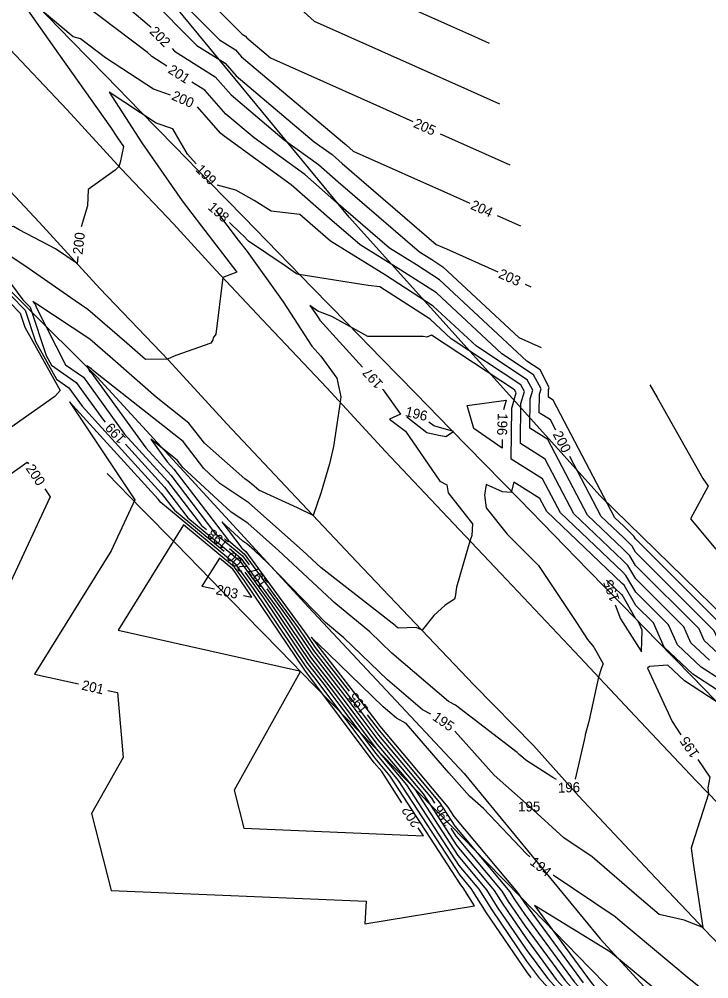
# Model space of a CAD drawing. Extents: x 2086416 to 2115205, y 575507 to 632762.
# Drawn here: x 2110108.6 to 2110247.4, y 582081.1 to 582274.4 of the extents above; entities that cross this region are included whole.
import ezdxf

# ---------------------------------------------------------------- set-up
doc = ezdxf.new("R2010")
doc.units = 0
for name, color, linetype in [('DTM Contours Major', 7, 'Continuous'), ('DTM Contours Major Text', 7, 'Continuous'), ('DTM Contours Minor', 7, 'Continuous'), ('DTM Contours Minor Text', 7, 'Continuous'), ('Exist Hydrographic FEMA Cross Section', 7, 'Continuous'), ('Exist Roads EOP', 7, 'Continuous'), ('Exist Vegetation Woods Line', 7, 'Continuous')]:
    doc.layers.add(name, color=color, linetype=linetype)

msp = doc.modelspace()

# ---------------------------------------------------------------- linework, layer by layer
at = {"layer": 'DTM Contours Major'}
for points in [[(2110109.16, 582313.08), (2110112.32, 582311.02), (2110129.31, 582294.29), (2110131.09, 582292.62), (2110132.72, 582292.09), (2110134.17, 582290.85), (2110153.5, 582271.34), (2110154.17, 582270.92), (2110154.43, 582270.61), (2110159.2, 582266.6), (2110181.16, 582256.77), (2110187.89, 582253.76)], [(2110139.1, 582259.08), (2110135.66, 582260.25), (2110126, 582266.59), (2110120.98, 582270.39), (2110119.48, 582270.82), (2110107.88, 582280.62), (2110107.79, 582280.67), (2110107.65, 582280.8), (2110106.39, 582281.73), (2110107.13, 582280.82), (2110107.89, 582279.73), (2110116.56, 582267.38), (2110127.02, 582252.6), (2110128.41, 582250.45), (2110129.6, 582248.74), (2110128.93, 582245.49), (2110128.68, 582244.73), (2110127.92, 582243.98), (2110122.51, 582240.09), (2110122.35, 582236.81), (2110121.07, 582232.55)], [(2110120.4, 582226.6), (2110120.27, 582225.14), (2110115.94, 582228.14), (2110108.58, 582231.97), (2110107.48, 582232.63), (2110107.15, 582232.52), (2110098.82, 582237.61), (2110091.52, 582245.28), (2110084.17, 582251.94), (2110069.86, 582265.54), (2110068.65, 582266.59), (2110065.58, 582269.39), (2110068.47, 582266.29), (2110068.49, 582266.13), (2110068.51, 582266.04), (2110068.58, 582265.96), (2110068.8, 582265.85), (2110068.96, 582265.74), (2110080.07, 582251.64), (2110082.51, 582248.8), (2110083.01, 582248.14)], [(2110216.68, 582191.59), (2110215.58, 582193.69), (2110213.31, 582195.12), (2110213.35, 582198.82), (2110213.67, 582199.92), (2110212.19, 582202.73), (2110205.75, 582206.99), (2110192.62, 582219.23), (2110185.46, 582223.85), (2110177.23, 582228.94), (2110171.12, 582234.2), (2110163.38, 582241.04), (2110149.85, 582250.84), (2110149.16, 582251.42), (2110144.51, 582256.72)], [(2110193.36, 582251.31), (2110197.45, 582249.48), (2110207.4, 582245.02)], [(2110086.65, 582243.38), (2110095.68, 582232.16), (2110101, 582226.63), (2110106.9, 582218.72), (2110109.82, 582215.75), (2110111.89, 582209.48), (2110116.13, 582201.87), (2110118.59, 582200.15), (2110121.31, 582196.4), (2110137.22, 582178.92), (2110139.86, 582175.47), (2110149.85, 582167.21)], [(2110099.85, 582145.93), (2110102.02, 582172.15), (2110103.18, 582180.21), (2110110.21, 582185.17), (2110110.46, 582184.79)], [(2110290, 582117.14), (2110289.15, 582117.29), (2110288.34, 582117.88), (2110287.04, 582119.12), (2110266.32, 582135.96), (2110264.06, 582137.88), (2110253.94, 582146.12), (2110251, 582148.03), (2110249.23, 582149.7), (2110248.56, 582151.2), (2110232.69, 582167.05), (2110231.99, 582168.26), (2110230.29, 582169.96), (2110225.81, 582174.22), (2110219.47, 582186.28)], [(2110113.79, 582179.8), (2110114.86, 582178.19), (2110099.85, 582145.93)], [(2110191.46, 582134.37), (2110189.8, 582135.29), (2110182.74, 582141.3), (2110173.98, 582149.79), (2110170.26, 582152.86), (2110158.63, 582164.85), (2110155.96, 582167.33), (2110154.43, 582168.68), (2110153.61, 582169.23), (2110149.41, 582173.13), (2110153.47, 582167.82), (2110154.26, 582167.17), (2110166.58, 582150.21), (2110168.17, 582147.85), (2110175.02, 582139.02)], [(2110154.04, 582162.97), (2110157.57, 582158.11), (2110166.69, 582144.59), (2110169.67, 582140.76), (2110180.39, 582126.46), (2110184.93, 582121.05), (2110197.34, 582101.97), (2110199.56, 582099.31), (2110202.62, 582094.39), (2110210.86, 582082.32), (2110211.34, 582081.67), (2110211.64, 582081.34)], [(2110233.92, 582146.96), (2110234.05, 582151.33), (2110233.23, 582153.16), (2110232.79, 582153.6), (2110229.98, 582158.41), (2110229.95, 582158.44), (2110226.85, 582161.39)], [(2110228.63, 582156.43), (2110229.67, 582153.63), (2110233.92, 582146.96)], [(2110303.45, 582097.38), (2110294.64, 582098.89), (2110286.31, 582105.05), (2110272.88, 582117.83), (2110266.32, 582123.16), (2110255.61, 582132.3), (2110253.76, 582133.81), (2110242.54, 582141.09), (2110239.17, 582144.26), (2110235.48, 582144.01), (2110235.12, 582143.67), (2110240.07, 582132.89), (2110241.85, 582130.25)], [(2110178.7, 582134.27), (2110181.09, 582131.08), (2110193.25, 582116.59), (2110196.34, 582111.83), (2110207.38, 582098.6), (2110208.2, 582097.27), (2110210.42, 582094.03), (2110220.36, 582080.52), (2110224.5, 582075.98), (2110233.47, 582064.23), (2110239.72, 582055.18)], [(2110245.21, 582125.28), (2110247.64, 582121.68), (2110247.24, 582119.54), (2110247.42, 582118.38), (2110244.01, 582107.89), (2110243.92, 582107.4), (2110244.29, 582104.39), (2110246.27, 582091.41), (2110242.5, 582092.91), (2110237.49, 582094.05), (2110233.41, 582097.47), (2110224, 582105.68), (2110218.29, 582109.52), (2110211.34, 582115.8), (2110211.3, 582115.8), (2110211.29, 582115.81), (2110211.29, 582115.84), (2110204.27, 582122.09), (2110196.34, 582130.95)], [(2110211.34, 582115.8), (2110211.29, 582115.84)]]:
    msp.add_lwpolyline(points, dxfattribs=at)
at = {"layer": 'DTM Contours Minor'}
for points in [[(2110105.69, 582354.06), (2110078.26, 582335.67), (2110072.95, 582330.04), (2110076.03, 582327.3), (2110083.75, 582320.11), (2110086.59, 582317.64), (2110093.04, 582313.86), (2110096.74, 582314), (2110100.17, 582310.68), (2110110.46, 582303.98), (2110118.21, 582296.35), (2110124.17, 582290.79), (2110129.58, 582289.03), (2110134.41, 582284.9), (2110148.95, 582270.22), (2110152.13, 582268.2), (2110153.38, 582266.78), (2110174.1, 582249.31), (2110174.35, 582249.12), (2110174.5, 582248.99), (2110175.87, 582247.81), (2110196.04, 582238.78), (2110199.37, 582237.29)], [(2110088.26, 582344.86), (2110071.39, 582333.56), (2110068.12, 582330.1), (2110075.14, 582323.86), (2110080.32, 582319.04), (2110088.41, 582311.98), (2110093.09, 582309.23), (2110095.99, 582306.9), (2110107.74, 582298), (2110108.83, 582297.19), (2110116.85, 582289.32), (2110117.24, 582288.95), (2110126.44, 582285.97), (2110134.65, 582278.95), (2110144.41, 582269.09), (2110150.09, 582265.48), (2110152.32, 582262.94), (2110168.03, 582249.69), (2110171.61, 582247.1), (2110173.66, 582245.29), (2110192.55, 582229.02), (2110194.63, 582228.09), (2110204.98, 582223.46)], [(2110070.82, 582335.67), (2110064.52, 582331.45), (2110063.29, 582330.15), (2110074.25, 582320.42), (2110076.9, 582317.96), (2110084.69, 582311.16), (2110089.77, 582305.9), (2110093.79, 582302.67), (2110100.55, 582297.54), (2110108.44, 582291.73), (2110114.07, 582286.19), (2110116.66, 582284.86), (2110121.29, 582283.56), (2110123.31, 582282.91), (2110134.88, 582273), (2110135.16, 582272.72)], [(2110150.46, 582311.41), (2110150.06, 582290.18), (2110168.03, 582273.97), (2110188.32, 582264.9), (2110198.85, 582260.18), (2110205.3, 582257.29)], [(2110178.18, 582290.91), (2110178.06, 582284.52), (2110186.24, 582277.15), (2110195.47, 582273.02), (2110200.26, 582270.87), (2110203.2, 582269.56)], [(2110055.08, 582277.12), (2110064.21, 582267.32), (2110064.38, 582265.25), (2110064.72, 582263.91), (2110065.6, 582262.82), (2110068.64, 582261.46), (2110070.76, 582259.93), (2110073.56, 582256.38), (2110079.18, 582249.83), (2110085.75, 582241.03), (2110091.49, 582233.9), (2110101.65, 582223.35), (2110104.47, 582219.58), (2110108.83, 582215.15), (2110109.74, 582212.36), (2110116.87, 582199.58), (2110115.81, 582198.41), (2110095.28, 582183.92), (2110094.13, 582175.93)], [(2110138.33, 582264.93), (2110135.33, 582266.84), (2110135.12, 582267.04), (2110134.42, 582267.65), (2110121.82, 582277.17)], [(2110139.38, 582268.46), (2110139.87, 582267.96), (2110148.05, 582262.77), (2110151.27, 582259.1), (2110161.97, 582250.07), (2110168.87, 582245.08), (2110172.81, 582241.6), (2110189.18, 582227.5), (2110191.7, 582225.94), (2110193.9, 582224.52), (2110209.23, 582210.23), (2110213.72, 582208.22)], [(2110251.63, 582150.81), (2110232.67, 582169.74), (2110232.39, 582170.23), (2110230.35, 582172.26), (2110228.56, 582173.97), (2110216.12, 582197.65), (2110215.19, 582198.24), (2110215.21, 582199.75), (2110215.34, 582200.19), (2110213.48, 582203.74), (2110210.84, 582205.48), (2110193.26, 582221.88), (2110188.58, 582224.89), (2110183.2, 582228.22), (2110171.96, 582237.9), (2110166.12, 582243.06), (2110155.91, 582250.46), (2110150.21, 582255.26), (2110146.01, 582260.05), (2110143.39, 582261.71)], [(2110144.27, 582245.25), (2110142.48, 582247.2), (2110139.57, 582252.28), (2110136.21, 582253.42), (2110126.7, 582259.67), (2110133.3, 582249.49), (2110141.43, 582237.79), (2110145.31, 582232.68), (2110152.45, 582223.39), (2110150.46, 582222.65), (2110149.62, 582222.32), (2110148.2, 582210.96), (2110147.68, 582210.21), (2110147.61, 582209.79), (2110147.18, 582209.14), (2110140.18, 582206.61), (2110138.64, 582205.95), (2110138.54, 582205.84), (2110138.27, 582205.9), (2110134.03, 582205.85), (2110130.31, 582209.12), (2110122.45, 582215.91), (2110119.87, 582217.62), (2110109.78, 582224.7), (2110101.02, 582230.38)], [(2110249.31, 582146.65), (2110246.54, 582149.25), (2110245.5, 582151.59), (2110232.71, 582164.36), (2110231.58, 582166.29), (2110230.22, 582167.65), (2110223.06, 582174.47), (2110215.05, 582189.72), (2110211.44, 582192), (2110211.49, 582197.9), (2110212, 582199.64), (2110210.91, 582201.73), (2110200.66, 582208.49), (2110191.98, 582216.59), (2110182.34, 582222.81), (2110171.26, 582229.66), (2110170.27, 582230.51), (2110165.12, 582235.06), (2110159.34, 582235.73), (2110155.89, 582237.85), (2110152.24, 582239.91), (2110148.54, 582240.92), (2110148.47, 582240.98)], [(2110148.15, 582235.89), (2110152.7, 582229.89), (2110154.49, 582227.57), (2110161.76, 582217.45), (2110167.51, 582208.51), (2110169.37, 582206.47), (2110172.55, 582202.06), (2110173.38, 582198.29), (2110173.24, 582197.24), (2110171.86, 582188.28), (2110171.08, 582184.8), (2110169.43, 582179.09), (2110167.82, 582174.41), (2110164.62, 582175.97), (2110156.87, 582179.5), (2110155.01, 582181.15), (2110154.03, 582181.8), (2110145.89, 582188.97), (2110142.78, 582193.04), (2110136.2, 582198.22), (2110126.91, 582206.38), (2110122.81, 582209.92), (2110112.15, 582217), (2110111.78, 582217.26), (2110111.39, 582217.51), (2110111.76, 582217.01), (2110111.82, 582216.95), (2110112.01, 582216.36), (2110117.94, 582204.78), (2110121.58, 582202.24), (2110129.85, 582190.82), (2110138.49, 582181.33), (2110145.31, 582172.41), (2110146.3, 582171.58)], [(2110204.84, 582234.84), (2110209.51, 582232.75)], [(2110247.62, 582145.26), (2110243.85, 582148.79), (2110242.43, 582151.98), (2110232.73, 582161.67), (2110231.18, 582164.32), (2110230.15, 582165.35), (2110220.31, 582174.72), (2110214.51, 582185.76), (2110209.56, 582188.88), (2110209.63, 582196.97), (2110210.34, 582199.37), (2110209.63, 582200.72), (2110195.57, 582209.99), (2110191.34, 582213.94), (2110181.24, 582220.46), (2110178.88, 582220.72), (2110164.9, 582222.92), (2110164.47, 582223.08), (2110162.14, 582224.71), (2110154.79, 582229.64), (2110153.76, 582230.71), (2110153.19, 582231.26), (2110150.97, 582233.41)], [(2110100.35, 582229.91), (2110109.33, 582217.86), (2110110.82, 582216.35), (2110114.03, 582206.61), (2110115.1, 582204.68), (2110120.09, 582201.2), (2110125.58, 582193.61), (2110125.95, 582193.21)], [(2110210.45, 582221.01), (2110211.61, 582220.49)], [(2110253.83, 582138.74), (2110245.92, 582143.87), (2110241.16, 582148.34), (2110239.36, 582152.37), (2110232.75, 582158.98), (2110230.78, 582162.35), (2110230.08, 582163.05), (2110217.56, 582174.97), (2110213.98, 582181.8), (2110207.68, 582185.76), (2110207.77, 582196.04), (2110208.67, 582199.09), (2110208.35, 582199.71), (2110191.62, 582210.75), (2110190.71, 582210.36), (2110189.95, 582210.48), (2110178.78, 582210.49), (2110171.53, 582214.5), (2110168.77, 582215.54), (2110167.12, 582216.69), (2110168.44, 582214.85), (2110169.14, 582213.76), (2110177.74, 582204.29)], [(2110181.77, 582199.85), (2110181.92, 582199.69), (2110185.41, 582194.85), (2110183.17, 582193.83), (2110186.37, 582191.37), (2110193.32, 582181.3), (2110194.74, 582180.62), (2110194.95, 582178.95), (2110199.87, 582172.71), (2110199.74, 582170.4), (2110199.37, 582169.27), (2110196.67, 582160), (2110196.41, 582158.03), (2110196.23, 582157.56), (2110194.4, 582156.32), (2110192.08, 582154.24), (2110189.75, 582151.3), (2110188.52, 582151.87), (2110184.89, 582151.74), (2110184.49, 582152.08), (2110184.42, 582152.15), (2110184.3, 582152.25), (2110169.43, 582163.86), (2110165.64, 582167.38), (2110154.82, 582176.99), (2110149, 582180.87), (2110145.76, 582183.88), (2110141.61, 582189.31), (2110124.29, 582202.95), (2110123.52, 582203.63), (2110123.17, 582203.93), (2110122.23, 582204.56), (2110122.77, 582203.5), (2110123.07, 582203.29), (2110134.13, 582188.02), (2110139.13, 582182.53), (2110148.03, 582170.88), (2110153.6, 582166.27), (2110154.91, 582164.47)], [(2110235.58, 582200.71), (2110237.04, 582198.16), (2110246.25, 582181.86), (2110247.35, 582180.34), (2110243.79, 582173.72), (2110248.85, 582167.62)], [(2110198, 582099.45), (2110197.53, 582100), (2110183.27, 582121.94), (2110180.25, 582125.54), (2110167.91, 582142), (2110166.4, 582143.94), (2110155.77, 582159.69), (2110152.29, 582164.48), (2110137.14, 582177), (2110136.59, 582177.72), (2110118.74, 582197.32), (2110131.92, 582177.57), (2110127.14, 582167.29), (2110111.7, 582142.48), (2110120.58, 582140.49)], [(2110200.12, 582191.93), (2110198.83, 582196.54), (2110206.67, 582197.67), (2110206.09, 582195.7)], [(2110186.64, 582194.25), (2110190.71, 582191.11)], [(2110190.71, 582191.11), (2110192.75, 582190.64), (2110194.54, 582190.3), (2110196.08, 582191.33), (2110192.07, 582192.49), (2110191.1, 582193.18)], [(2110205.87, 582189.73), (2110205.85, 582187.95), (2110200.12, 582191.93)], [(2110216.79, 582121.22), (2110216.05, 582121.67), (2110210.62, 582125.15), (2110209.52, 582126.06), (2110209.52, 582126.06), (2110209.24, 582126.3), (2110208.9, 582126.68), (2110196.45, 582136.19), (2110195.04, 582136.98), (2110183.61, 582146.69), (2110179.2, 582150.97), (2110171.95, 582156.97), (2110171.57, 582157.35), (2110160.8, 582167.35), (2110154.62, 582172.84), (2110151.31, 582175.05), (2110141.57, 582184.1), (2110140.44, 582185.58), (2110135.1, 582189.79), (2110138.4, 582185.23), (2110139.76, 582183.73), (2110150.75, 582169.35), (2110153.93, 582166.72), (2110164.78, 582151.79), (2110167.87, 582147.2), (2110176.71, 582135.81), (2110180.95, 582130.15), (2110191.59, 582117.48), (2110192.24, 582116.48)], [(2110129.99, 582188.77), (2110137.86, 582180.13), (2110142.58, 582173.94), (2110152.95, 582165.38), (2110159.37, 582156.53), (2110166.99, 582145.24), (2110171.43, 582139.52), (2110180.53, 582127.38), (2110186.6, 582120.16), (2110197.14, 582103.95), (2110201.12, 582099.16), (2110203.74, 582094.97), (2110210.77, 582084.66), (2110213.14, 582081.44), (2110222.72, 582070.93), (2110225.66, 582067.07), (2110236.67, 582051.15), (2110214.22, 582039.54)], [(2110253.79, 582136.27), (2110244.23, 582142.48), (2110238.48, 582147.89), (2110236.3, 582152.77), (2110232.77, 582156.29), (2110230.38, 582160.38), (2110230.02, 582160.74), (2110214.81, 582175.22), (2110213.44, 582177.83), (2110208.22, 582181.12), (2110207.69, 582179.06), (2110205.89, 582179.18), (2110202.62, 582180.63), (2110202.32, 582178.51), (2110202.63, 582175.96), (2110206.85, 582170.62), (2110213.18, 582164.35), (2110220.8, 582152.86), (2110223.04, 582149.46), (2110224.29, 582147.92), (2110226.16, 582144.56), (2110225.87, 582143.7), (2110225.27, 582141.82), (2110223.28, 582132.9), (2110222.58, 582130.23), (2110222.57, 582130.16), (2110222.56, 582130.13), (2110222.38, 582129.14), (2110220.55, 582121.33)], [(2110181.61, 582122.84), (2110180.11, 582124.62), (2110166.14, 582143.24), (2110166.1, 582143.29), (2110153.97, 582161.27), (2110151.96, 582164.03), (2110141.71, 582172.5), (2110128.55, 582151.34), (2110165.07, 582143.15), (2110165.1, 582142.79), (2110151.87, 582119.09), (2110153.82, 582111.44), (2110190.02, 582109.89), (2110188.96, 582111.53)], [(2110150.93, 582167.76), (2110153.27, 582165.82), (2110161.17, 582154.95), (2110167.28, 582145.9), (2110173.19, 582138.29), (2110180.67, 582128.31), (2110188.26, 582119.27), (2110196.94, 582105.92), (2110202.69, 582099.02), (2110204.85, 582095.54), (2110210.68, 582087), (2110214.95, 582081.21), (2110223.16, 582072.19), (2110227.61, 582066.36), (2110241.27, 582046.6), (2110242.14, 582045.61), (2110244.26, 582042.28), (2110214.02, 582011.24)], [(2110152.17, 582162.85), (2110151.64, 582163.58), (2110148.91, 582165.84), (2110145.4, 582160.2), (2110147.92, 582159.64)], [(2110153.77, 582158.32), (2110155.48, 582157.94), (2110152.17, 582162.85)], [(2110158.44, 582159.61), (2110162.98, 582153.37), (2110167.58, 582146.55), (2110174.95, 582137.05), (2110180.81, 582129.23), (2110189.92, 582118.37), (2110196.74, 582107.89), (2110204.25, 582098.88), (2110205.97, 582096.12), (2110210.59, 582089.35), (2110216.75, 582080.98), (2110223.61, 582073.45), (2110229.57, 582065.65), (2110241.24, 582048.76), (2110244.31, 582045.24), (2110251.86, 582033.4), (2110241.09, 582022.35), (2110222.86, 582001.98)], [(2110211.44, 582105.68), (2110210.75, 582106.3), (2110210.73, 582106.3), (2110202.09, 582115.38), (2110202.08, 582115.39), (2110202.09, 582115.4), (2110199.29, 582117.88), (2110195.08, 582122.59), (2110186.55, 582132.5), (2110184.56, 582133.61), (2110181.86, 582135.9), (2110168.76, 582148.6), (2110168.57, 582148.76), (2110167.43, 582149.94), (2110168.38, 582148.63), (2110168.46, 582148.5), (2110180.23, 582133.34), (2110181.24, 582132), (2110194.91, 582115.69), (2110196.14, 582113.8), (2110208.94, 582098.45), (2110209.32, 582097.85), (2110210.33, 582096.37), (2110222.16, 582080.29)], [(2110126.43, 582139.17), (2110128.4, 582138.73), (2110129.52, 582125.69), (2110123.2, 582114.37), (2110127.13, 582098.91), (2110178.47, 582096.72), (2110178.22, 582092.14), (2110200.27, 582095.79), (2110198, 582099.45)], [(2110185.68, 582116.56), (2110181.61, 582122.84)], [(2110195.51, 582111.45), (2110196.54, 582109.86), (2110205.81, 582098.74), (2110207.08, 582096.7), (2110210.51, 582091.69), (2110218.55, 582080.75), (2110224.05, 582074.71), (2110231.52, 582064.94), (2110241.21, 582050.92), (2110246.49, 582044.86), (2110254.2, 582032.77), (2110254.23, 582032.74), (2110256.28, 582030.31), (2110264.15, 582018.43), (2110254.35, 582019.56), (2110220.3, 581977.38), (2110206.86, 581962.37)], [(2110247.4, 582078), (2110243.48, 582081.11), (2110232.4, 582090.33), (2110229.6, 582092.68), (2110228.58, 582093.57), (2110216.12, 582101.96)], [(2110239.63, 582076.69), (2110234.85, 582080.48), (2110227.63, 582086.48), (2110212.34, 582095.86), (2110223.97, 582080.06), (2110225.38, 582078.5), (2110237.38, 582062.8), (2110241.12, 582057.39), (2110253.02, 582043.75), (2110256.71, 582037.96), (2110256.86, 582037.78), (2110266.82, 582025.99), (2110275.38, 582013.07), (2110279.92, 582006.23), (2110285.03, 581998.78), (2110298.39, 581976.04), (2110298.49, 581975.89), (2110298.8, 581975.39), (2110299.81, 581973.62), (2110296.89, 581973.45), (2110283.89, 581972.66)]]:
    msp.add_lwpolyline(points, dxfattribs=at)
at = {"layer": 'Exist Hydrographic FEMA Cross Section'}
for points in [[(2110250.95, 582134.94), (2110244.01, 582142.05), (2110237.07, 582149.16), (2110230.14, 582156.27), (2110223.19, 582163.38), (2110216.26, 582170.5), (2110209.32, 582177.61), (2110202.38, 582184.72), (2110195.44, 582191.83), (2110188.5, 582198.95), (2110181.56, 582206.06), (2110174.62, 582213.17), (2110167.68, 582220.28), (2110160.74, 582227.39), (2110153.81, 582234.51), (2110146.86, 582241.62), (2110139.93, 582248.73), (2110132.99, 582255.84), (2110126.05, 582262.96), (2110119.11, 582270.07), (2110112.17, 582277.18)], [(2110230.4, 582076.22), (2110223.46, 582083.33), (2110216.53, 582090.44), (2110209.58, 582097.55), (2110202.65, 582104.66), (2110195.71, 582111.78), (2110188.77, 582118.89), (2110181.83, 582126), (2110174.89, 582133.11), (2110167.95, 582140.23), (2110161.01, 582147.34), (2110154.07, 582154.45), (2110147.14, 582161.56), (2110140.2, 582168.68), (2110133.26, 582175.78), (2110126.32, 582182.9)]]:
    msp.add_lwpolyline(points, dxfattribs=at)
at = {"layer": 'Exist Roads EOP'}
for points in [[(2110283.42, 582080.08), (2110269.79, 582094.77), (2110258.57, 582106.89), (2110244.84, 582121.04), (2110232.61, 582133.97), (2110220.43, 582147.01), (2110205.56, 582162.74), (2110193.7, 582175.26), (2110182.38, 582187.32), (2110170.57, 582200.14), (2110157.55, 582213.9), (2110148.13, 582223.91), (2110139.67, 582233.18), (2110129.17, 582244.2), (2110118.25, 582256.11), (2110105.57, 582269.53), (2110093.37, 582282.59), (2110082.14, 582294.76), (2110071.88, 582305.53), (2110059.32, 582319.17)], [(2110044.03, 582306.54), (2110057.72, 582292.25), (2110067.42, 582282.08), (2110077.05, 582271.73), (2110082.67, 582265.54), (2110091.18, 582256.81), (2110101.9, 582244.92), (2110112.61, 582233.51), (2110124.83, 582220.15), (2110138.66, 582205.71), (2110150.44, 582192.87), (2110163.31, 582179.2), (2110176.51, 582165.18), (2110187.09, 582154.1), (2110200.16, 582140.29), (2110212.15, 582128.06), (2110221.2, 582117.92), (2110235.62, 582102.6), (2110247.94, 582089.65), (2110262.41, 582074.68), (2110272.71, 582063.48), (2110283.25, 582052.48)]]:
    msp.add_lwpolyline(points, dxfattribs=at)
at = {"layer": 'Exist Vegetation Woods Line'}
for points in [[(2110284.48, 582120.87), (2110225.58, 582178.38), (2110175.08, 582234.49), (2110136.61, 582281.24), (2110106.48, 582313.41), (2110078.56, 582339.36)], [(2110068.55, 582251.65), (2110094.73, 582231.68), (2110124.29, 582202.28), (2110166.88, 582155.97), (2110198.23, 582122.47), (2110225.6, 582089.15), (2110269.57, 582041.09)]]:
    msp.add_lwpolyline(points, dxfattribs=at)

# ---------------------------------------------------------------- texts
at = {"layer": 'DTM Contours Major Text'}
for s, rotation, p in [('200', 336.4209, (2110139.15, 582258.24)), ('205', 335.8814, (2110187.84, 582252.69)), ('200', 83.5266, (2110121.36, 582226.89)), ('200', 297.7124, (2110215.98, 582190.78)), ('200', 303.7059, (2110109.85, 582183.91)), ('200', 134.6269, (2110154.71, 582164.15)), ('195', 109.7652, (2110229.51, 582157.5)), ('195', 127.7584, (2110179.05, 582135.46)), ('195', 324.989, (2110191.65, 582133.39)), ('195', 124.0436, (2110245.63, 582126.44))]:
    msp.add_text(s, height=2, rotation=rotation, dxfattribs=at).set_placement(p)
msp.add_text('195', height=2, dxfattribs=at).set_placement((2110209.06, 582114.8))
at = {"layer": 'DTM Contours Minor Text'}
for s, rotation, p in [('202', 314.7306, (2110134.72, 582271.74)), ('201', 327.5741, (2110138.41, 582263.69)), ('199', 314.5413, (2110143.99, 582243.95)), ('204', 335.8846, (2110199.32, 582236.22)), ('198', 318.6348, (2110146.44, 582236.25)), ('203', 335.8846, (2110204.93, 582222.38)), ('197', 132.2462, (2110182.03, 582201.06)), ('196', 346.4707, (2110186.2, 582194.46)), ('196', 267.8759, (2110204.98, 582195.04)), ('199', 132.3216, (2110130.24, 582189.98)), ('198', 140.4308, (2110151.01, 582168.99)), ('197', 125.9879, (2110158.82, 582160.78)), ('203', 347.3513, (2110148.08, 582158.58)), ('201', 347.3513, (2110121.07, 582139.35)), ('196', 1.7073, (2110217.1, 582118.58)), ('202', 123.0288, (2110189.58, 582112.41)), ('196', 123.0288, (2110195.95, 582112.6)), ('194', 321.5276, (2110211.26, 582104.3))]:
    msp.add_text(s, height=2, rotation=rotation, dxfattribs=at).set_placement(p)

doc.saveas('drawing.dxf')
